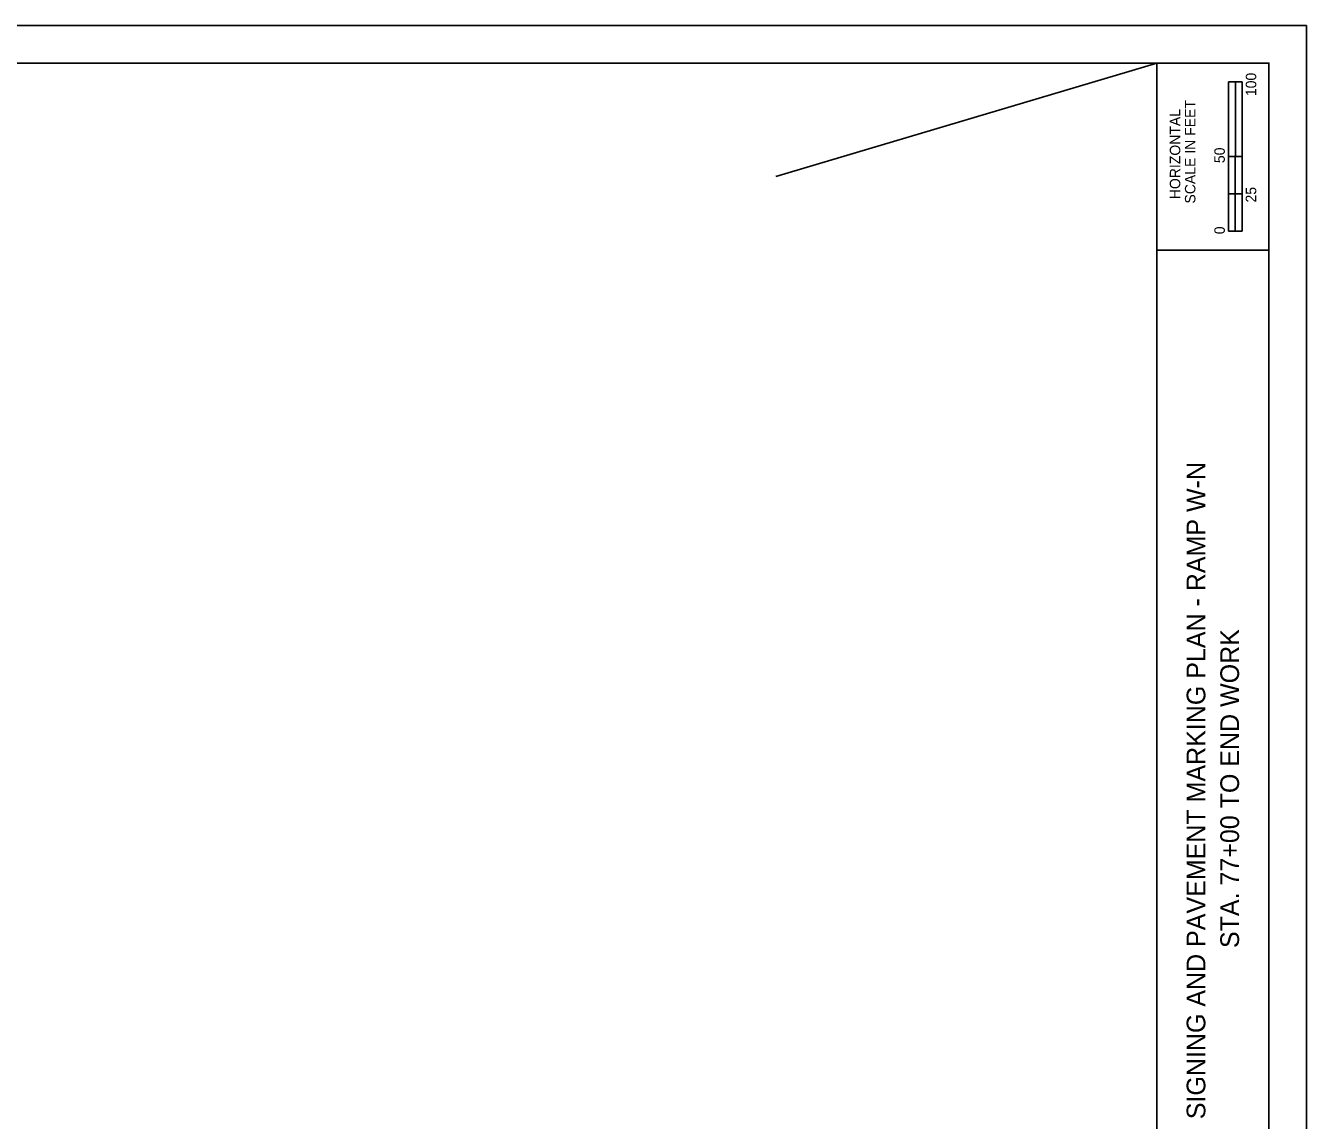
# Model space of a CAD drawing. Extents: x -0.2 to 34, y 0 to 22.
# Drawn here: x 16.88 to 34, y 7.36 to 22 of the extents above; entities that cross this region are included whole.
import ezdxf

# ---------------------------------------------------------------- set-up
doc = ezdxf.new("R2010")
doc.units = 0
for name, color, linetype in [('SC_Scratch1', 7, 'Continuous'), ('SH_Border', 7, 'Continuous'), ('SH_Cut_Line', 7, 'Continuous'), ('SH_Data', 7, 'Continuous')]:
    doc.layers.add(name, color=color, linetype=linetype)

msp = doc.modelspace()

# ---------------------------------------------------------------- linework, layer by layer
at = {"layer": 'SC_Scratch1'}
msp.add_line((26.908, 19.984), (32, 21.5), dxfattribs=at)
msp.add_lwpolyline([(32, 21.5), (1.5, 21.5), (1.5, 0.5), (32, 0.5)], close=True, dxfattribs=at)
at = {"layer": 'SH_Border'}
for p, q in [((32, 0.5), (32, 21.5)), ((32, 19), (33.5, 19))]:
    msp.add_line(p, q, dxfattribs=at)
msp.add_lwpolyline([(1.5, 21.5), (33.5, 21.5), (33.5, 0.5), (1.5, 0.5)], close=True, dxfattribs=at)
at = {"layer": 'SH_Cut_Line'}
msp.add_lwpolyline([(0, 0), (34, 0), (34, 22), (0, 22)], close=True, dxfattribs=at)
at = {"layer": 'SH_Data'}
for p, q in [((32.957, 19.25), (32.957, 21.25)), ((33.144, 21.25), (32.957, 21.25)), ((32.957, 20.25), (32.957, 21.25)), ((32.957, 21.25), (33.05, 21.25)), ((33.05, 21.25), (33.051, 21.25)), ((33.051, 21.25), (33.051, 20.25)), ((33.144, 21.25), (33.144, 19.25)), ((33.051, 20.25), (32.957, 20.25)), ((33.143, 20.25), (33.05, 20.25)), ((33.05, 20.25), (33.05, 19.75)), ((33.143, 19.75), (33.143, 20.25)), ((33.05, 19.75), (32.957, 19.75)), ((32.957, 19.75), (32.957, 19.25)), ((33.05, 19.25), (33.05, 19.75)), ((33.05, 19.75), (33.143, 19.75)), ((33.144, 19.25), (32.957, 19.25)), ((32.957, 19.25), (33.05, 19.25))]:
    msp.add_line(p, q, dxfattribs=at)

# ---------------------------------------------------------------- texts
for s, height, p in [('100', 0.14, (33.33, 21.057)), ('SCALE IN FEET', 0.14, (32.517, 19.621)), ('HORIZONTAL', 0.14, (32.315, 19.679)), ('50', 0.14, (32.91, 20.162)), ('25', 0.14, (33.33, 19.635)), ('0', 0.14, (32.91, 19.211)), ('SIGNING AND PAVEMENT MARKING PLAN - RAMP W-N', 0.25, (32.65, 7.38)), ('STA. 77+00 TO END WORK', 0.25, (33.1, 9.668))]:
    msp.add_text(s, height=height, rotation=90, dxfattribs=at).set_placement(p)

doc.saveas('drawing.dxf')
